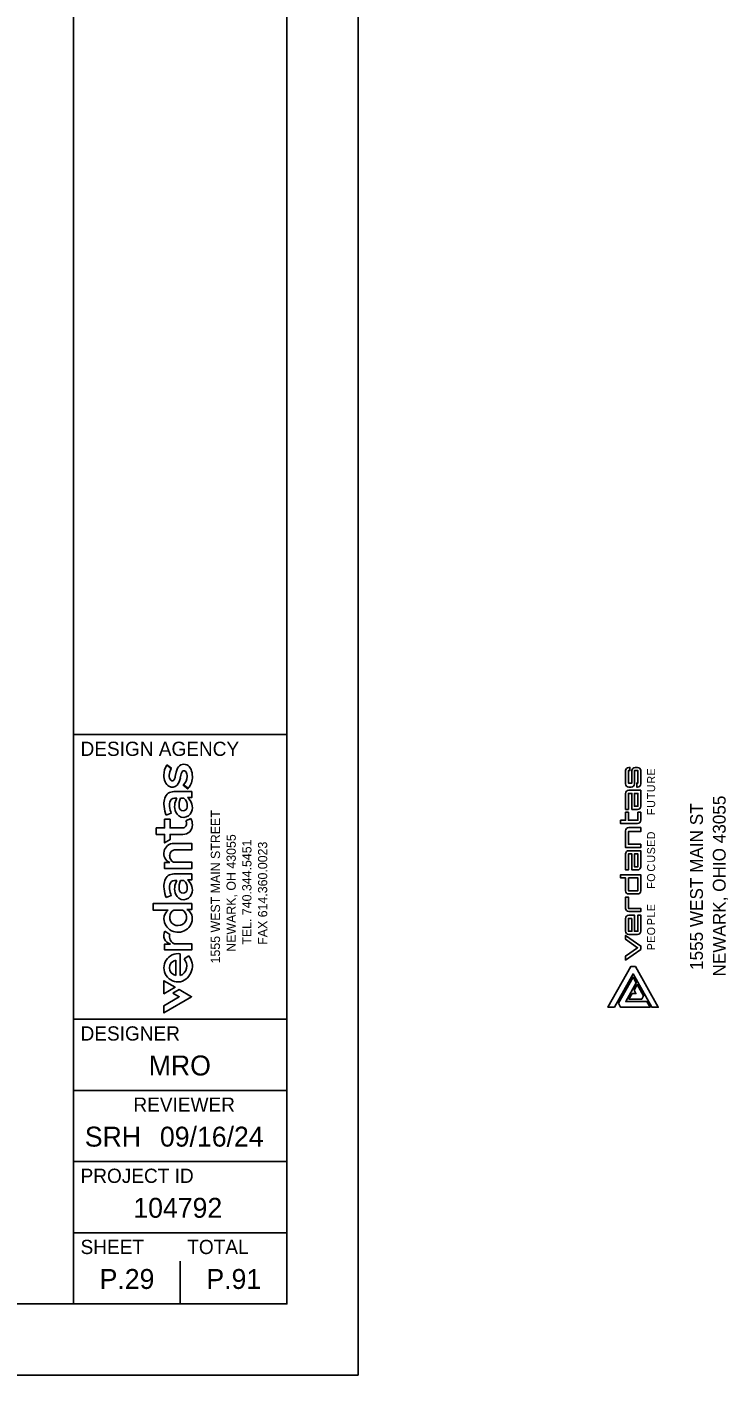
# Model space of a CAD drawing. Extents: x 0 to 36.6, y 0 to 22.
# Drawn here: x 31.67 to 36.6, y 0 to 9.47 of the extents above; entities that cross this region are included whole.
import ezdxf

# ---------------------------------------------------------------- set-up
doc = ezdxf.new("R2010")
doc.units = 0
for name, color, linetype in [('CS-ANNO-TTLB-LOGO', 7, 'Continuous'), ('Default', 7, 'Continuous'), ('SH_Border', 7, 'Continuous'), ('SH_Cut_Line', 7, 'Continuous'), ('SH_Data', 7, 'Continuous'), ('SH_Text', 7, 'Continuous')]:
    doc.layers.add(name, color=color, linetype=linetype)

msp = doc.modelspace()

# ---------------------------------------------------------------- linework, layer by layer
at = {"layer": 'CS-ANNO-TTLB-LOGO'}
for p, q in [((35.9113, 4.269), (35.9028, 4.269)), ((35.9647, 4.269), (35.9478, 4.269)), ((35.8803, 4.2465), (35.8803, 4.1537)), ((35.9872, 4.1537), (35.9872, 4.2465)), ((35.8803, 3.9737), (35.8803, 4.0862)), ((35.9028, 4.1312), (35.9197, 4.1312)), ((35.8803, 3.549), (35.8803, 3.6615)), ((35.9028, 3.3802), (35.9647, 3.3802)), ((35.9872, 3.1187), (35.9872, 3.2312)), ((35.8803, 3.2087), (35.8803, 3.1187)), ((35.9028, 3.0962), (35.9647, 3.0962))]:
    msp.add_line(p, q, dxfattribs=at)
for points in [[(35.9253, 4.2465), (35.9253, 4.1594), (35.9, 4.1594), (35.9, 4.2465), (35.9113, 4.2465), (35.9113, 4.269)], [(35.9422, 4.1537), (35.9422, 4.2465), (35.9675, 4.2465), (35.9675, 4.1594), (35.9591, 4.1594), (35.9591, 4.1312), (35.9647, 4.1312)], [(35.9647, 3.9737), (35.9253, 3.9737), (35.9253, 4.0862), (35.9, 4.0862), (35.9, 3.9737), (35.8803, 3.9737)], [(35.9028, 4.1087), (35.9872, 4.1087), (35.9872, 3.9962)], [(35.8456, 3.8977), (35.8803, 3.8977), (35.8803, 3.954), (35.9, 3.954), (35.9, 3.8977), (35.9675, 3.8977), (35.9675, 3.954), (35.9872, 3.954), (35.9872, 3.8977)], [(35.9647, 3.8752), (35.8456, 3.8752), (35.8456, 3.8977)], [(35.8803, 3.8246), (35.8803, 3.7065), (35.9872, 3.7065), (35.9872, 3.729), (35.9, 3.729), (35.9, 3.819), (35.9872, 3.819)], [(35.9872, 3.819), (35.9872, 3.8471), (35.9028, 3.8471)], [(35.9647, 3.549), (35.9253, 3.549), (35.9253, 3.6615), (35.9, 3.6615), (35.9, 3.549), (35.8803, 3.549)], [(35.9028, 3.684), (35.9872, 3.684), (35.9872, 3.5715)], [(35.8456, 3.5152), (35.8456, 3.4927), (35.8803, 3.4927), (35.8803, 3.4027)], [(35.9872, 3.4027), (35.9872, 3.5152), (35.8456, 3.5152)], [(35.9872, 3.279), (35.9, 3.279), (35.9, 3.3577), (35.8803, 3.3577), (35.8803, 3.279)], [(35.9028, 3.2565), (35.9872, 3.2565), (35.9872, 3.279)], [(35.9872, 3.2312), (35.9675, 3.2312), (35.9675, 3.1187), (35.9422, 3.1187), (35.9422, 3.2312), (35.9028, 3.2312)]]:
    msp.add_lwpolyline(points, dxfattribs=at)
for points in [[(35.9422, 4.0862), (35.9675, 4.0862), (35.9675, 3.9962), (35.9422, 3.9962)], [(35.9422, 3.6615), (35.9675, 3.6615), (35.9675, 3.5715), (35.9422, 3.5715)], [(35.9, 3.4927), (35.9, 3.4027), (35.9675, 3.4027), (35.9675, 3.4927)], [(35.9253, 3.2087), (35.9, 3.2087), (35.9, 3.1187), (35.9253, 3.1187)], [(35.9648, 3.0024), (35.8803, 2.9433), (35.8803, 2.9158), (35.9872, 2.9907), (35.9877, 3.0139), (35.8808, 3.0887), (35.8803, 3.0615)]]:
    msp.add_lwpolyline(points, close=True, dxfattribs=at)
for centre, start, end in [((35.9028, 4.2465), 90, 180), ((35.9478, 4.2465), 90, 180), ((35.9647, 4.2465), 360, 90), ((35.9028, 4.1537), 180, 270), ((35.9028, 4.0862), 90, 180), ((35.9197, 4.1537), 270, 0), ((35.9647, 4.1537), 270, 0), ((35.9647, 3.9962), 270, 360), ((35.9647, 3.8977), 270, 360), ((35.9028, 3.8246), 90, 180), ((35.9028, 3.6615), 90, 180), ((35.9647, 3.5715), 270, 360), ((35.9028, 3.4027), 180, 270), ((35.9647, 3.4027), 270, 0), ((35.9028, 3.279), 180, 270), ((35.9028, 3.2087), 90, 180), ((35.9028, 3.1187), 180, 270), ((35.9647, 3.1187), 270, 0)]:
    msp.add_arc(centre, 0.0225, start, end, dxfattribs=at)
at = {"layer": 'Default'}
for p, q in [((35.9647, 4.269), (35.9478, 4.269)), ((35.8803, 4.2465), (35.8803, 4.1537)), ((35.9872, 4.1537), (35.9872, 4.2465)), ((35.9028, 4.1312), (35.9197, 4.1312)), ((35.9028, 3.3802), (35.9647, 3.3802)), ((35.8803, 3.2087), (35.8803, 3.1187)), ((35.9028, 3.0962), (35.9647, 3.0962)), ((35.8298, 2.6122), (35.9331, 2.7954)), ((35.9557, 2.7554), (35.8816, 2.6239)), ((35.9331, 2.7954), (35.9557, 2.7554)), ((35.8454, 2.5845), (35.8298, 2.6122)), ((36.0521, 2.5845), (35.8454, 2.5845)), ((35.8816, 2.6239), (36.0299, 2.6239)), ((36.0299, 2.6239), (36.0521, 2.5845))]:
    msp.add_line(p, q, dxfattribs=at)
for points in [[(35.9253, 4.2465), (35.9253, 4.1594), (35.9, 4.1594), (35.9, 4.2465), (35.9113, 4.2465), (35.9113, 4.269), (35.9028, 4.269)], [(35.9422, 4.1537), (35.9422, 4.2465), (35.9675, 4.2465), (35.9675, 4.1594), (35.9591, 4.1594), (35.9591, 4.1312), (35.9647, 4.1312)], [(35.8803, 4.0862), (35.8803, 3.9737), (35.9, 3.9737), (35.9, 4.0862), (35.9253, 4.0862), (35.9253, 3.9737), (35.9647, 3.9737)], [(35.9872, 3.9962), (35.9872, 4.1087), (35.9028, 4.1087)], [(35.9872, 3.8977), (35.9872, 3.954), (35.9675, 3.954), (35.9675, 3.8977), (35.9, 3.8977), (35.9, 3.954), (35.8803, 3.954), (35.8803, 3.8977), (35.8456, 3.8977), (35.8456, 3.8752), (35.9647, 3.8752)], [(35.8803, 3.8246), (35.8803, 3.7065), (35.9872, 3.7065), (35.9872, 3.729), (35.9, 3.729), (35.9, 3.819), (35.9872, 3.819), (35.9872, 3.8471), (35.9028, 3.8471)], [(35.8803, 3.6615), (35.8803, 3.549), (35.9, 3.549), (35.9, 3.6615), (35.9253, 3.6615), (35.9253, 3.549), (35.9647, 3.549)], [(35.9872, 3.5715), (35.9872, 3.684), (35.9028, 3.684)], [(35.9872, 3.4027), (35.9872, 3.5152), (35.8456, 3.5152), (35.8456, 3.4927), (35.8803, 3.4927), (35.8803, 3.4027)], [(35.9028, 3.2565), (35.9872, 3.2565), (35.9872, 3.279), (35.9, 3.279), (35.9, 3.3577), (35.8803, 3.3577), (35.8803, 3.279)], [(35.9872, 3.1187), (35.9872, 3.2312), (35.9675, 3.2312), (35.9675, 3.1187), (35.9422, 3.1187), (35.9422, 3.2312), (35.9028, 3.2312)]]:
    msp.add_lwpolyline(points, dxfattribs=at)
for points in [[(35.9675, 4.0862), (35.9675, 3.9962), (35.9422, 3.9962), (35.9422, 4.0862)], [(35.9675, 3.6615), (35.9675, 3.5715), (35.9422, 3.5715), (35.9422, 3.6615)], [(35.9, 3.4927), (35.9675, 3.4927), (35.9675, 3.4027), (35.9, 3.4027)], [(35.9253, 3.2087), (35.9253, 3.1187), (35.9, 3.1187), (35.9, 3.2087)], [(35.8803, 2.9433), (35.8803, 2.9158), (35.9872, 2.9907), (35.9877, 3.0139), (35.8808, 3.0887), (35.8803, 3.0615), (35.9648, 3.0024)], [(35.9331, 2.8183), (36.065, 2.5845), (36.1102, 2.5845), (35.9493, 2.8699), (35.917, 2.8699), (35.7561, 2.5845), (35.8013, 2.5845)], [(35.8013, 2.5845), (35.9331, 2.8183), (36.065, 2.5845), (36.1102, 2.5845), (35.9493, 2.8699), (35.917, 2.8699), (35.7561, 2.5845)], [(35.8298, 2.6122), (35.8454, 2.5845), (36.0521, 2.5845), (36.0299, 2.6239), (35.8816, 2.6239), (35.9557, 2.7554), (35.9331, 2.7954)], [(35.9262, 2.6802), (35.904, 2.6408), (35.9944, 2.6408), (36.0074, 2.6638), (35.9622, 2.7439), (35.9396, 2.7038), (35.953, 2.6802)], [(35.9262, 2.6802), (35.953, 2.6802), (35.9396, 2.7038), (35.9622, 2.7439), (36.0074, 2.6638), (35.9944, 2.6408), (35.904, 2.6408)]]:
    msp.add_lwpolyline(points, close=True, dxfattribs=at)
for centre, start, end in [((35.9028, 4.2465), 90, 180), ((35.9478, 4.2465), 90, 180), ((35.9647, 4.2465), 360, 90), ((35.9028, 4.1537), 180, 270), ((35.9028, 4.0862), 90, 180), ((35.9197, 4.1537), 270, 0), ((35.9647, 4.1537), 270, 0), ((35.9647, 3.9962), 270, 0), ((35.9647, 3.8977), 270, 0), ((35.9028, 3.8246), 90, 180), ((35.9028, 3.6615), 90, 180), ((35.9647, 3.5715), 270, 0), ((35.9028, 3.4027), 180, 270), ((35.9647, 3.4027), 270, 0), ((35.9028, 3.279), 180, 270), ((35.9028, 3.2087), 90, 180), ((35.9028, 3.1187), 180, 270), ((35.9647, 3.1187), 270, 0)]:
    msp.add_arc(centre, 0.0225, start, end, dxfattribs=at)
at = {"layer": 'SH_Border'}
for p, q in [((32, 0.5), (32, 21.5)), ((32, 4.5), (33.5, 4.5)), ((32, 2.5), (33.5, 2.5)), ((32, 2), (33.5, 2)), ((32, 1.5), (33.5, 1.5)), ((32, 1), (33.5, 1))]:
    msp.add_line(p, q, dxfattribs=at)
msp.add_lwpolyline([(1.5, 21.5), (33.5, 21.5), (33.5, 0.5), (1.5, 0.5)], close=True, dxfattribs=at)
at = {"layer": 'SH_Cut_Line'}
msp.add_lwpolyline([(0, 0), (34, 0), (34, 22), (0, 22)], close=True, dxfattribs=at)
at = {"layer": 'SH_Data'}
for p, q in [((32.75, 3.5), (32.75, 3.5)), ((32.75, 0.5), (32.75, 0.8)), ((32.375, 0.675), (32.375, 0.675))]:
    msp.add_line(p, q, dxfattribs=at)
at = {"layer": 'SH_Text'}
for p, q in [((32.6876, 4.2619), (32.6565, 4.2855)), ((32.722, 4.2361), (32.7153, 4.2049)), ((32.7512, 4.1942), (32.7555, 4.2142)), ((32.7738, 4.1463), (32.8065, 4.1225)), ((32.7112, 4.0538), (32.7272, 4.0538)), ((32.7527, 4.0538), (32.7757, 4.0538)), ((32.6474, 3.9459), (32.6522, 3.9339)), ((32.8248, 3.9101), (32.7897, 3.8939)), ((32.7112, 3.4753), (32.7272, 3.4753)), ((32.7527, 3.4753), (32.7757, 3.4753)), ((32.6474, 3.3674), (32.6522, 3.3554)), ((32.7056, 3.267), (32.766, 3.267)), ((32.6785, 3.0958), (32.6415, 3.1181)), ((32.7508, 2.8071), (32.7508, 2.9601)), ((32.8102, 2.9454), (32.7779, 2.9232)), ((32.7205, 2.9152), (32.7205, 2.8079))]:
    msp.add_line(p, q, dxfattribs=at)
for points in [[(32.6893, 4.2644), (32.6575, 4.2868), (32.6565, 4.2855)], [(32.6876, 4.2619), (32.6893, 4.2644)], [(32.722, 4.2361), (32.7153, 4.2049)], [(32.7512, 4.1942), (32.7555, 4.2142)], [(32.8009, 4.0576), (32.8311, 4.0576), (32.8311, 4.0993), (32.706, 4.0993)], [(32.8009, 4.0576), (32.8311, 4.0576), (32.8311, 4.0993), (32.706, 4.0993)], [(32.7738, 4.1463), (32.7715, 4.1438), (32.803, 4.1188), (32.8065, 4.1225)], [(32.7112, 4.0538), (32.7272, 4.0538)], [(32.7757, 4.0538), (32.7527, 4.0538)], [(32.7614, 3.8444), (32.6795, 3.8444), (32.6795, 3.9054), (32.6406, 3.9054), (32.6406, 3.8444), (32.5823, 3.8444), (32.5823, 3.799), (32.6406, 3.799), (32.6406, 3.7393), (32.6796, 3.7627), (32.6796, 3.799), (32.7694, 3.799)], [(32.7614, 3.8444), (32.6795, 3.8444), (32.6795, 3.9054), (32.6406, 3.9054), (32.6406, 3.8444), (32.5823, 3.8444), (32.5823, 3.799), (32.6406, 3.799), (32.6406, 3.7393), (32.6796, 3.7627), (32.6796, 3.799), (32.7694, 3.799)], [(32.6474, 3.9459), (32.6522, 3.9339)], [(32.6522, 3.9339), (32.6878, 3.9483), (32.6841, 3.9577)], [(32.6522, 3.9339), (32.6878, 3.9483), (32.6841, 3.9577)], [(32.8248, 3.9101), (32.7897, 3.8939)], [(32.7194, 3.6901), (32.8311, 3.6901), (32.8311, 3.7356), (32.7067, 3.7356)], [(32.7194, 3.6901), (32.8311, 3.6901), (32.8311, 3.7356), (32.7067, 3.7356)], [(32.6779, 3.6007), (32.6406, 3.6007), (32.6406, 3.5586), (32.8311, 3.5586), (32.8311, 3.6041), (32.7037, 3.6041)], [(32.6779, 3.6007), (32.6406, 3.6007), (32.6406, 3.5586), (32.8311, 3.5586), (32.8311, 3.6041), (32.7037, 3.6041)], [(32.8009, 3.4791), (32.8311, 3.4791), (32.8311, 3.5208), (32.706, 3.5208)], [(32.8009, 3.4791), (32.8311, 3.4791), (32.8311, 3.5208), (32.706, 3.5208)], [(32.7112, 3.4753), (32.7272, 3.4753)], [(32.7757, 3.4753), (32.7527, 3.4753)], [(32.6474, 3.3674), (32.6522, 3.3554)], [(32.6522, 3.3554), (32.6878, 3.3698), (32.6841, 3.3792)], [(32.6522, 3.3554), (32.6878, 3.3698), (32.6841, 3.3792)], [(32.6668, 3.267), (32.5598, 3.267), (32.5598, 3.3125), (32.8311, 3.3125), (32.831, 3.2709), (32.7975, 3.2708)], [(32.7975, 3.2708), (32.831, 3.2709), (32.8311, 3.3125), (32.5598, 3.3125), (32.5598, 3.267), (32.6668, 3.267)], [(32.7056, 3.267), (32.766, 3.267)], [(32.6785, 3.0958), (32.6415, 3.1181)], [(32.6813, 3.0285), (32.6405, 3.0285), (32.6405, 2.987), (32.831, 2.987), (32.831, 3.0309), (32.7048, 3.0309)], [(32.6813, 3.0285), (32.6405, 3.0285), (32.6405, 2.987), (32.831, 2.987), (32.831, 3.0309), (32.7048, 3.0309)], [(32.7508, 2.8071), (32.7508, 2.9601)], [(32.8102, 2.9454), (32.7779, 2.9232)], [(32.7205, 2.8079), (32.7205, 2.9152)], [(32.6355, 2.7702), (32.6355, 2.6794), (32.7142, 2.7248), (32.6355, 2.7702)], [(32.6994, 2.6833), (32.744, 2.6575), (32.6355, 2.5949), (32.6355, 2.5448), (32.8308, 2.6575), (32.7428, 2.7083), (32.6994, 2.6833)]]:
    msp.add_lwpolyline(points, dxfattribs=at)
for points in [[(32.7142, 2.7248), (32.6355, 2.6794), (32.6355, 2.7702)], [(32.6994, 2.6833), (32.744, 2.6575), (32.6355, 2.5949), (32.6355, 2.5448), (32.8308, 2.6575), (32.7428, 2.7083)]]:
    msp.add_lwpolyline(points, close=True, dxfattribs=at)
for centre, radius, start, end in [((32.7669, 4.2144), 0.1313, 147.22328, 179.84204), ((32.7669, 4.2144), 0.1313, 147.22328, 179.84204), ((32.8485, 4.2074), 0.1296, 154.04469, 167.21491), ((32.8485, 4.2074), 0.1296, 154.04469, 167.21491), ((32.7762, 4.2427), 0.0493, 52.70919, 154.21664), ((32.7762, 4.2427), 0.0493, 52.70919, 154.21664), ((32.7611, 4.2269), 0.0711, 22.82777, 50.71565), ((32.7611, 4.2269), 0.0711, 22.82777, 50.71565), ((32.7495, 4.2128), 0.1139, 179.01095, 203.55998), ((32.7495, 4.2128), 0.1139, 179.01095, 203.55998), ((32.7435, 4.2137), 0.0702, 179.05393, 195.69208), ((32.7435, 4.2137), 0.0702, 179.05393, 195.69208), ((32.7681, 4.2118), 0.0948, 148.12326, 178.11353), ((32.7681, 4.2118), 0.0948, 148.12326, 178.11353), ((32.7085, 4.2028), 0.0335, 193.85614, 223.71908), ((32.7085, 4.2028), 0.0335, 193.85614, 223.71908), ((32.6948, 4.19), 0.0148, 224.78223, 330.43657), ((32.6948, 4.19), 0.0148, 224.78223, 330.43657), ((32.6348, 4.22), 0.0819, 332.90022, 349.38313), ((32.6348, 4.22), 0.0819, 332.90022, 349.38313), ((32.6477, 4.2131), 0.1053, 320.12588, 349.70225), ((32.6477, 4.2131), 0.1053, 320.12588, 349.70225), ((32.8492, 4.1988), 0.0949, 158.18628, 170.63281), ((32.8492, 4.1988), 0.0949, 158.18628, 170.63281), ((32.7769, 4.2294), 0.0165, 26.91646, 163.60196), ((32.7769, 4.2294), 0.0165, 26.91646, 163.60196), ((32.7053, 4.2094), 0.0932, 317.36304, 356.92436), ((32.7053, 4.2094), 0.0932, 317.36304, 356.92436), ((32.7329, 4.2078), 0.0655, 357.00773, 26.31116), ((32.7329, 4.2078), 0.0655, 357.00773, 26.31116), ((32.7066, 4.2048), 0.1295, 320.51657, 0.43409), ((32.7066, 4.2048), 0.1295, 320.51657, 0.43409), ((32.7164, 4.2078), 0.1196, 359.0192, 22.9257), ((32.7164, 4.2078), 0.1196, 359.0192, 22.9257), ((32.7038, 4.0354), 0.0639, 88.07599, 162.86424), ((32.7038, 4.0354), 0.0639, 88.07599, 162.86424), ((32.7066, 4.1939), 0.067, 203.36923, 237.807), ((32.7066, 4.1939), 0.067, 203.36923, 237.807), ((32.6946, 4.1764), 0.0458, 238.94525, 317.68291), ((32.6946, 4.1764), 0.0458, 238.94525, 317.68291), ((32.7639, 4.012), 0.1283, 160.81276, 180.93166), ((32.7639, 4.012), 0.1283, 160.81276, 180.93166), ((32.8342, 4.0132), 0.1986, 180.9467, 199.83537), ((32.8342, 4.0132), 0.1986, 180.9467, 199.83537), ((32.7389, 4.0073), 0.0647, 163.25224, 179.99706), ((32.7389, 4.0073), 0.0647, 163.25224, 179.99706), ((32.8257, 4.0117), 0.1516, 181.66161, 200.87137), ((32.8257, 4.0117), 0.1516, 181.66161, 200.87137), ((32.7131, 4.0164), 0.0374, 92.96709, 165.223), ((32.7131, 4.0164), 0.0374, 92.96709, 165.223), ((32.8196, 3.9969), 0.1085, 148.34975, 202.47075), ((32.8196, 3.9969), 0.1085, 148.34975, 202.47075), ((32.8468, 4.0076), 0.1048, 153.83718, 188.87457), ((32.8468, 4.0076), 0.1048, 153.83718, 188.87457), ((32.7712, 3.9925), 0.0281, 182.32704, 355.37776), ((32.7712, 3.9925), 0.0281, 182.32704, 355.37776), ((32.7369, 4.0034), 0.0637, 348.12474, 52.36783), ((32.7369, 4.0034), 0.0637, 348.12474, 52.36783), ((32.7503, 3.9885), 0.0857, 338.27739, 53.79489), ((32.7503, 3.9885), 0.0857, 338.27739, 53.79489), ((32.7744, 3.9773), 0.0592, 201.67635, 339.72677), ((32.7744, 3.9773), 0.0592, 201.67635, 339.72677), ((32.7523, 3.8723), 0.0432, 1.86376, 29.96515), ((32.7523, 3.8723), 0.0432, 1.86376, 29.96515), ((32.7422, 3.8657), 0.0939, 359.5424, 28.24947), ((32.7422, 3.8657), 0.0939, 359.5424, 28.24947), ((32.7641, 3.8757), 0.0314, 265.06923, 356.35481), ((32.7641, 3.8757), 0.0314, 265.06923, 356.35481), ((32.7718, 3.8632), 0.0642, 267.86409, 1.62134), ((32.7718, 3.8632), 0.0642, 267.86409, 1.62134), ((32.7055, 3.6653), 0.0703, 88.98961, 246.91113), ((32.7055, 3.6653), 0.0703, 88.98961, 246.91113), ((32.7196, 3.6493), 0.0434, 137.30492, 182.96879), ((32.7196, 3.6493), 0.0434, 137.30492, 182.96879), ((32.724, 3.6473), 0.0477, 180.34657, 244.91134), ((32.724, 3.6473), 0.0477, 180.34657, 244.91134), ((32.7171, 3.6469), 0.0433, 86.97388, 132.7421), ((32.7171, 3.6469), 0.0433, 86.97388, 132.7421), ((32.7038, 3.4569), 0.0639, 88.07599, 162.86424), ((32.7038, 3.4569), 0.0639, 88.07599, 162.86424), ((32.7639, 3.4336), 0.1283, 160.81276, 180.93166), ((32.7639, 3.4336), 0.1283, 160.81276, 180.93166), ((32.8342, 3.4347), 0.1986, 180.9467, 199.83537), ((32.8342, 3.4347), 0.1986, 180.9467, 199.83537), ((32.7389, 3.4288), 0.0647, 163.25224, 179.99706), ((32.7389, 3.4288), 0.0647, 163.25224, 179.99706), ((32.8257, 3.4332), 0.1516, 181.66161, 200.87137), ((32.8257, 3.4332), 0.1516, 181.66161, 200.87137), ((32.7131, 3.4379), 0.0374, 92.96709, 165.223), ((32.7131, 3.4379), 0.0374, 92.96709, 165.223), ((32.8196, 3.4184), 0.1085, 148.34975, 202.47075), ((32.8196, 3.4184), 0.1085, 148.34975, 202.47075), ((32.8468, 3.4291), 0.1048, 153.83718, 188.87457), ((32.8468, 3.4291), 0.1048, 153.83718, 188.87457), ((32.7712, 3.414), 0.0281, 182.32704, 355.37776), ((32.7712, 3.414), 0.0281, 182.32704, 355.37776), ((32.7369, 3.4249), 0.0637, 348.12474, 52.36783), ((32.7369, 3.4249), 0.0637, 348.12474, 52.36783), ((32.7503, 3.41), 0.0857, 338.27739, 53.79489), ((32.7503, 3.41), 0.0857, 338.27739, 53.79489), ((32.7744, 3.3988), 0.0592, 201.67635, 339.72677), ((32.7744, 3.3988), 0.0592, 201.67635, 339.72677), ((32.707, 3.208), 0.0714, 124.28433, 181.27226), ((32.707, 3.208), 0.0714, 124.28433, 181.27226), ((32.7358, 3.217), 0.0595, 176.4529, 5.05495), ((32.7358, 3.217), 0.0595, 176.4529, 5.05495), ((32.7349, 3.2162), 0.0586, 119.90067, 175.57974), ((32.7349, 3.2162), 0.0586, 119.90067, 175.57974), ((32.7366, 3.2161), 0.0588, 6.06662, 60.04101), ((32.7366, 3.2161), 0.0588, 6.06662, 60.04101), ((32.7687, 3.2103), 0.0671, 5.30838, 64.52521), ((32.7687, 3.2103), 0.0671, 5.30838, 64.52521), ((32.7356, 3.2113), 0.1001, 182.77189, 2.9779), ((32.7356, 3.2113), 0.1001, 182.77189, 2.9779), ((32.6973, 3.0892), 0.0628, 152.6524, 255.29294), ((32.6973, 3.0892), 0.0628, 152.6524, 255.29294), ((32.7303, 3.0791), 0.0545, 162.13838, 242.04081), ((32.7303, 3.0791), 0.0545, 162.13838, 242.04081), ((32.7353, 2.8617), 0.0996, 81.04458, 280.25771), ((32.7353, 2.8617), 0.0996, 81.04458, 280.25771), ((32.7223, 2.8733), 0.1138, 285.66678, 39.36993), ((32.7223, 2.8733), 0.1138, 285.66678, 39.36993), ((32.7288, 2.8616), 0.0543, 98.83779, 261.16221), ((32.7288, 2.8616), 0.0543, 98.83779, 261.16221), ((32.725, 2.8744), 0.072, 290.92317, 42.73906), ((32.725, 2.8744), 0.072, 290.92317, 42.73906)]:
    msp.add_arc(centre, radius, start, end, dxfattribs=at)

# ---------------------------------------------------------------- texts
at = {"layer": 'Default'}
for s, p in [('E', (36.0879, 4.2117)), ('R', (36.0879, 4.1558)), ('U', (36.0879, 4.0949)), ('T', (36.0879, 4.0464)), ('U', (36.0879, 3.9855)), ('F', (36.0879, 3.9343)), ('D', (36.0879, 3.764)), ('S', (36.0879, 3.6587)), ('E', (36.0879, 3.7113)), ('U', (36.0879, 3.6001)), ('C', (36.0879, 3.537)), ('O', (36.0879, 3.4659)), ('F', (36.0879, 3.417)), ('E', (36.0879, 3.259)), ('L', (36.0879, 3.2137)), ('O', (36.0879, 3.0896)), ('P', (36.0879, 3.1609)), ('E', (36.0879, 3.0367)), ('P', (36.0879, 2.9839))]:
    msp.add_text(s, height=0.0563, rotation=90, dxfattribs=at).set_placement(p)
at = {"layer": 'SH_Data'}
for s, height, p in [('DESIGN AGENCY', 0.1, (32.05, 4.35)), ('DESIGNER', 0.1, (32.05, 2.35)), ('MRO', 0.14, (32.5292, 2.105)), ('REVIEWER', 0.1, (32.4218, 1.85)), ('SRH', 0.14, (32.08, 1.605)), ('09/16/24', 0.14, (32.6078, 1.605)), ('PROJECT ID', 0.1, (32.05, 1.35)), ('104792', 0.14, (32.4209, 1.105)), ('SHEET', 0.1, (32.05, 0.85)), ('TOTAL', 0.1, (32.8, 0.85)), ('P.29', 0.14, (32.184, 0.605)), ('P.91', 0.14, (32.9344, 0.605))]:
    msp.add_text(s, height=height, dxfattribs=at).set_placement(p)
at = {"layer": 'SH_Text'}
for s, height, p in [('1555 WEST MAIN ST', 0.09, (36.4237, 2.8463)), ('NEWARK, OHIO 43055', 0.09, (36.5837, 2.8002)), ('1555 WEST MAIN STREET', 0.064969, (33.0304, 2.8921)), ('NEWARK, OH 43055', 0.064969, (33.1409, 2.974)), ('TEL. 740.344.5451', 0.064969, (33.2512, 3.0237)), ('FAX 614.360.0023', 0.064969, (33.3619, 3.023))]:
    msp.add_text(s, height=height, rotation=90, dxfattribs=at).set_placement(p)

doc.saveas('drawing.dxf')
